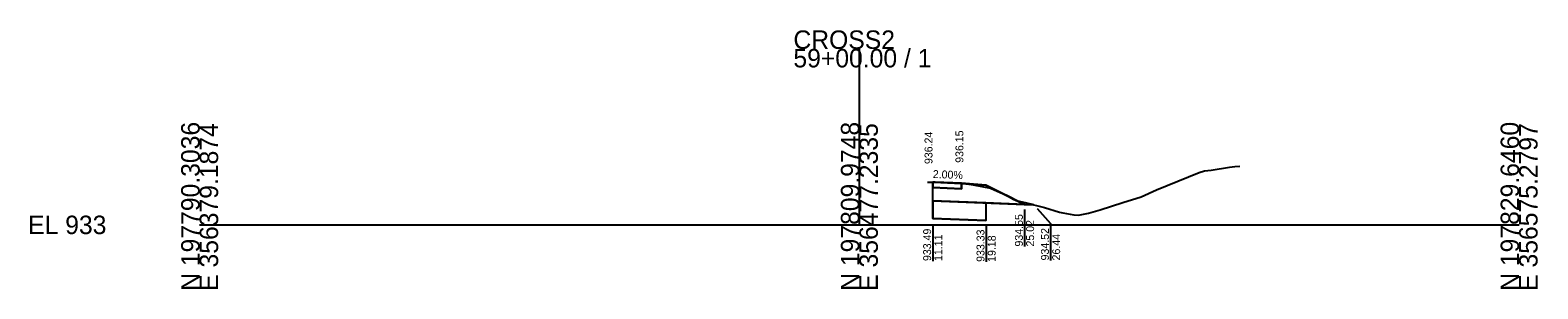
# Model space of a CAD drawing. Extents: x -26 to 203, y -10 to 14021.
# Drawn here: x -25.7 to 202.8, y -9.7 to 29.5 of the extents above; entities that cross this region are included whole.
import ezdxf

# ---------------------------------------------------------------- set-up
doc = ezdxf.new("R2010")
doc.units = 0
for name, color, linetype in [('Default', 7, 'Continuous'), ('P_E_XS_Ground', 7, 'Continuous'), ('P_XS', 7, 'Continuous'), ('P_XS_EAR_CommonGrnd', 7, 'Continuous'), ('P_XS_Lane', 7, 'Continuous'), ('P_XS_Rock', 7, 'Continuous')]:
    doc.layers.add(name, color=color, linetype=linetype)

msp = doc.modelspace()

# ---------------------------------------------------------------- linework, layer by layer
at = {"layer": 'Default'}
for p, q in [((100, 0), (100, 26.66)), ((0, 0), (100, 0)), ((100, 0), (200, 0))]:
    msp.add_line(p, q, dxfattribs=at)
at = {"layer": 'P_E_XS_Ground'}
for p, q in [((145.05, 5.33), (151.51, 7.94)), ((151.51, 7.94), (152.29, 8.17)), ((152.29, 8.17), (153.34, 8.31)), ((153.34, 8.31), (156.1, 8.72)), ((156.1, 8.72), (156.89, 8.83)), ((156.89, 8.83), (157.65, 8.89)), ((110.33, 6.49), (111.27, 6.48)), ((111.27, 6.48), (113.35, 6.36)), ((113.35, 6.36), (115.62, 6.27)), ((115.62, 6.27), (116.59, 6.16)), ((116.59, 6.16), (117.27, 6.09)), ((117.27, 6.09), (119.87, 5.58)), ((119.87, 5.58), (122.27, 4.5)), ((142.73, 4.26), (145.05, 5.33)), ((122.27, 4.5), (123.29, 3.9)), ((123.29, 3.9), (124.04, 3.58)), ((124.04, 3.58), (125.17, 3.36)), ((125.17, 3.36), (128.06, 2.62)), ((128.06, 2.62), (130.35, 1.93)), ((136.49, 2.28), (139.93, 3.4)), ((139.93, 3.4), (142.73, 4.26)), ((130.35, 1.93), (130.85, 1.84)), ((130.85, 1.84), (132.53, 1.54)), ((132.53, 1.54), (133.2, 1.49)), ((133.2, 1.49), (133.95, 1.63)), ((133.95, 1.63), (134.72, 1.77)), ((134.72, 1.77), (136.49, 2.28))]:
    msp.add_line(p, q, dxfattribs=at)
at = {"layer": 'P_XS'}
for p, q in [((111.11, 6.48), (111.11, 5.65)), ((111.11, 5.65), (115.5, 5.47)), ((111.11, 3.65), (111.11, 5.65)), ((115.5, 6.31), (115.5, 5.47)), ((111.11, 3.65), (125.02, 3.09)), ((111.11, 3.65), (111.11, 0.98)), ((119.18, 3.33), (119.18, 0.66)), ((111.11, 0.98), (119.18, 0.66))]:
    msp.add_line(p, q, dxfattribs=at)
at = {"layer": 'P_XS_EAR_CommonGrnd'}
for points in [[(111.11, 6.48), (111.27, 6.48), (111.47, 6.47)], [(111.47, 6.47), (113.35, 6.36), (115.5, 6.28), (115.5, 5.47), (111.11, 5.65), (111.11, 6.48)], [(124.04, 3.58), (125.02, 3.09), (119.18, 3.33), (111.11, 3.65), (111.11, 5.65), (115.5, 5.47), (115.5, 6.28), (115.62, 6.27), (116.59, 6.16), (117.27, 6.09), (119.87, 5.58), (121.68, 4.76), (122.63, 4.29), (123.29, 3.9)], [(111.47, 6.47), (113.35, 6.36), (115.5, 6.28), (115.5, 6.31)], [(115.5, 6.28), (115.62, 6.27), (116.59, 6.16), (117.27, 6.09), (119.87, 5.58), (121.68, 4.76), (119.18, 6.01), (115.5, 6.31)], [(121.68, 4.76), (122.27, 4.5), (122.63, 4.29)], [(119.18, 3.33), (119.18, 0.66), (111.11, 0.98), (111.11, 3.65)], [(122.63, 4.29), (123.29, 3.9), (124.04, 3.58)], [(124.04, 3.58), (125.02, 3.09), (126.44, 3.04), (125.17, 3.36)]]:
    msp.add_lwpolyline(points, close=True, dxfattribs=at)
at = {"layer": 'P_XS_Lane'}
for p, q in [((111.11, 6.48), (115.5, 6.31)), ((115.5, 6.31), (119.18, 6.01)), ((119.18, 6.01), (125.02, 3.09)), ((125.02, 3.09), (126.44, 3.04))]:
    msp.add_line(p, q, dxfattribs=at)
at = {"layer": 'P_XS_Rock'}
for p, q in [((125.03, 2.31), (125.03, -3.28)), ((126.93, 2.49), (128.98, 0.2)), ((111.12, 0.11), (111.12, -5.48)), ((128.98, 0.2), (128.98, -5.39)), ((119.21, -0.01), (119.21, -5.61))]:
    msp.add_line(p, q, dxfattribs=at)

# ---------------------------------------------------------------- texts
at = {"layer": 'Default'}
for s, p in [('CROSS2', (90, 26.66)), ('59+00.00 / 1', (90, 23.86)), ('EL 933', (-26, -1.4))]:
    msp.add_text(s, height=2.8, dxfattribs=at).set_placement(p)
for s, p in [('N 197790.3036', (0, -10)), ('E 356379.1874', (2.8, -10)), ('N 197809.9748', (100, -10)), ('E 356477.2335', (102.8, -10)), ('N 197829.6460', (200, -10)), ('E 356575.2797', (202.8, -10))]:
    msp.add_text(s, height=2.8, rotation=90, dxfattribs=at).set_placement(p)
at = {"layer": 'P_XS_Rock'}
for s, rotation, p in [('936.24', 90, (111.08, 9.21)), ('936.15', 90, (115.76, 9.4)), ('2.00%', 357.7094, (111.11, 7.11)), ('934.55', 90, (124.78, -3.28)), ('25.02', 90, (126.48, -3.28)), ('933.49', 90, (110.87, -5.48)), ('11.11', 90, (112.57, -5.48)), ('933.33', 90, (118.96, -5.61)), ('19.18', 90, (120.66, -5.61)), ('934.52', 90, (128.73, -5.39)), ('26.44', 90, (130.43, -5.39))]:
    msp.add_text(s, height=1.2, rotation=rotation, dxfattribs=at).set_placement(p)

doc.saveas('drawing.dxf')
